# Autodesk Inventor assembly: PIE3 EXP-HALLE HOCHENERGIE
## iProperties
Shininess: 64.0
Length Units: 11269
Angle Units: 11279
Time Units: 11290
Mass Units: 11286
Length Display Precision: 3
Angle Display Precision: 2
Compacted: True
Part Number: PIE3 EXP-HALLE HOCHENERGIE
Document SubType Name: Assembly
Created: 2004-08
Designer: John Blackburn
Manufacturer: Standard
Standards Organization: Custom
Density: 0.0
Volumn: 0.0
Area: 0.0
PropertySet Name: Model Information
Control State: 0
Master: False
Checked Out: False
Author: John Blackburn
